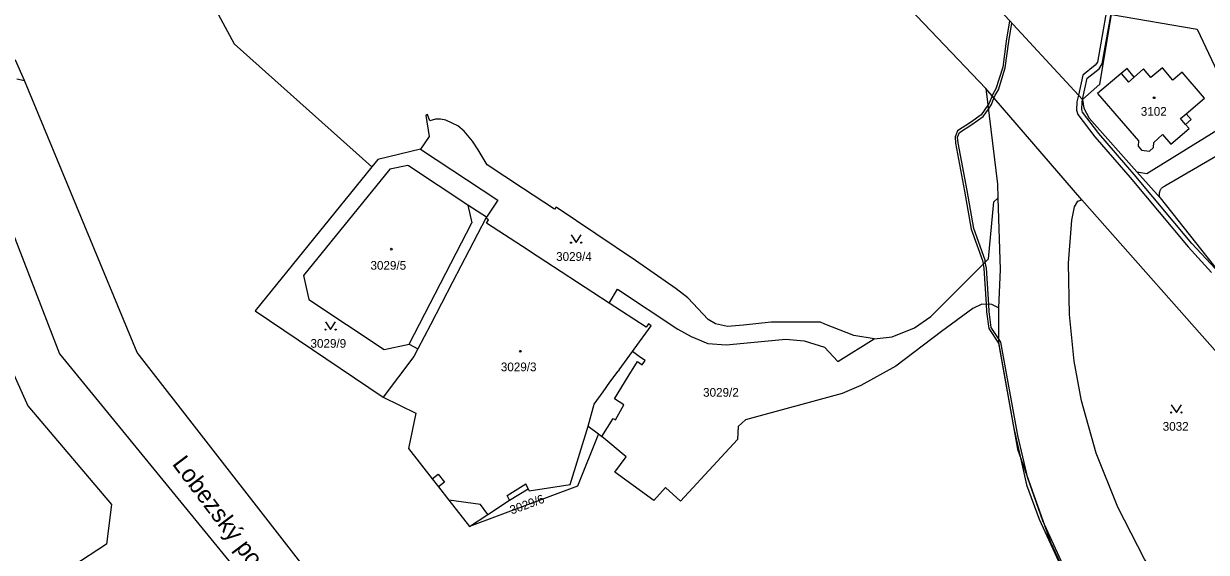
# Model space of a CAD drawing. Extents: x -869103 to -863415, y -1015889 to -1012477.
# Drawn here: x -866992.3 to -866761.8, y -1014341 to -1014238 of the extents above; entities that cross this region are included whole.
import ezdxf

# ---------------------------------------------------------------- set-up
doc = ezdxf.new("R2010")
doc.units = 0
for name, color, linetype in [('Hranice parcel', 7, 'Continuous'), ('Parcelní čísla', 7, 'Continuous'), ('Pop  PČ popisy', 7, 'Continuous'), ('Vnitřní kresba', 7, 'Continuous'), ('Věcná břemena k části', 7, 'Continuous'), ('Značky budov', 7, 'Continuous'), ('Značky kultur', 7, 'Continuous')]:
    doc.layers.add(name, color=color, linetype=linetype)

msp = doc.modelspace()

# ---------------------------------------------------------------- linework, layer by layer
at = {"layer": 'Hranice parcel'}
for p, q in [((-866964.38, -1014217.69), (-866951.31, -1014241.98)), ((-866802.65, -1014234.76), (-866785.95, -1014252.79)), ((-866951.31, -1014241.98), (-866924.44, -1014265.92)), ((-866970.19, -1014302.07), (-866992.13, -1014249.12)), ((-866786.04, -1014272.37), (-866804.77, -1014250.67)), ((-866802.4, -1014272.01), (-866801.98, -1014285.91)), ((-866786.04, -1014272.37), (-866743.88, -1014320.01)), ((-866902.08, -1014275.74), (-866902.24, -1014275.9)), ((-866801.98, -1014285.91), (-866802.31, -1014293.4)), ((-866880.29, -1014317.92), (-866879.64, -1014318.4))]:
    msp.add_line(p, q, dxfattribs=at)
for points in [[(-867024.12, -1014103.23), (-867025.22, -1014106.66), (-867026.7, -1014110.06), (-867027.68, -1014113.98), (-867028.22, -1014118.6), (-867028.54, -1014131.39), (-867028.57, -1014139.98), (-867029.17, -1014140.61), (-867028.61, -1014175.02), (-867028.14, -1014185.17), (-867027.28, -1014193.35), (-867026.52, -1014197.65), (-867025.07, -1014203.92), (-867022.09, -1014213.15), (-867017.38, -1014224.52), (-867004.44, -1014249.09), (-867006.1, -1014248.94), (-867004.52, -1014252.89), (-867004.05, -1014254.08), (-866985.31, -1014302.3), (-866931.57, -1014367.99)], [(-866992.13, -1014249.12), (-866993.94, -1014245.11), (-866995.31, -1014245.64), (-867000.95, -1014239.81), (-867007.7, -1014227.79), (-867011.08, -1014220.99), (-867014.34, -1014213.16), (-867017.24, -1014203.32), (-867020.06, -1014192.16), (-867021.01, -1014182.17), (-867021.12, -1014175.42), (-867020.1, -1014140.5)], [(-866785.95, -1014252.79), (-866782.53, -1014249.83), (-866780.28, -1014236.23), (-866774.28, -1014200.77)], [(-866804.77, -1014250.67), (-866827.62, -1014226.66), (-866838.88, -1014204.15)], [(-866772.86, -1014262.83), (-866772.07, -1014262.16), (-866772.04, -1014261.16), (-866770.36, -1014259.62), (-866768.71, -1014261.53), (-866765.14, -1014258.44), (-866765.82, -1014257.65), (-866764.74, -1014256.72), (-866765.71, -1014255.58), (-866762.17, -1014252.56), (-866766.52, -1014247.5), (-866768.29, -1014249.01), (-866770.33, -1014246.6), (-866772.58, -1014248.54), (-866774.02, -1014246.85), (-866775.84, -1014248.42), (-866777.2, -1014246.74), (-866778.37, -1014247.73), (-866782.99, -1014251.61), (-866775, -1014260.85), (-866775.09, -1014261.92), (-866774.44, -1014262.65), (-866772.86, -1014262.83)], [(-866804.77, -1014250.67), (-866802.48, -1014269.28), (-866802.4, -1014272.01)], [(-866785.95, -1014252.79), (-866785.66, -1014254.51), (-866784.65, -1014256.46), (-866775.31, -1014266.88), (-866770.78, -1014271.95), (-866748.88, -1014299.59)], [(-866826.54, -1014299.41), (-866830.52, -1014298.76), (-866836.15, -1014296.55), (-866837.01, -1014296.17), (-866846.62, -1014296.18), (-866852.01, -1014296.78), (-866855.15, -1014297.04), (-866857.48, -1014296.47), (-866858.89, -1014295.66), (-866862.85, -1014291.42), (-866865.11, -1014289.65), (-866873.08, -1014284.15), (-866888.52, -1014273.74), (-866888.83, -1014274.16), (-866895.1, -1014270.06), (-866901.95, -1014265.51), (-866903.72, -1014262.58), (-866904.81, -1014260.94), (-866906.45, -1014258.96), (-866907.69, -1014257.96), (-866908.79, -1014257.38), (-866910.01, -1014256.84), (-866911.07, -1014256.65), (-866912.04, -1014256.65), (-866913.17, -1014256.95), (-866913.61, -1014255.7), (-866913.96, -1014255.91), (-866913.31, -1014260.01), (-866914.94, -1014262.48)], [(-866914.94, -1014262.48), (-866923.29, -1014264.5), (-866924.44, -1014265.92)], [(-866914.94, -1014262.48), (-866899.88, -1014272.4), (-866902.08, -1014275.74)], [(-866924.44, -1014265.92), (-866947.22, -1014293.94), (-866922.25, -1014310.74)], [(-866902.08, -1014275.74), (-866905.72, -1014273.37), (-866917.32, -1014265.7), (-866917.42, -1014265.66), (-866920.96, -1014266.39), (-866937.78, -1014287.08), (-866936.73, -1014291.78), (-866922.04, -1014301.49), (-866917.2, -1014300.45), (-866915.47, -1014301.35)], [(-866815.46, -1014295.07), (-866804.23, -1014283.81), (-866803.19, -1014272.71), (-866802.4, -1014272.01)], [(-867008.33, -1014274.01), (-867004.45, -1014276.58), (-866995.06, -1014304.46), (-866991.53, -1014312.47), (-866975.18, -1014331.69), (-866976.17, -1014339.4), (-866989.29, -1014348), (-867029.58, -1014342.1), (-867038.07, -1014339.07), (-867056.98, -1014311.75)], [(-866763.74, -1014351.64), (-866766.16, -1014351.83), (-866767.82, -1014351.02), (-866769.8, -1014348.61), (-866773.81, -1014342.3), (-866779.03, -1014332.18), (-866783.24, -1014321.66), (-866786.09, -1014311.51), (-866787.58, -1014303.77), (-866788.49, -1014294.7), (-866788.64, -1014284.67), (-866787.99, -1014276.32), (-866787.46, -1014273.73), (-866786.86, -1014272.6), (-866786.04, -1014272.37)], [(-866902.24, -1014275.9), (-866908.74, -1014288.39), (-866913.05, -1014296.66), (-866915.47, -1014301.35)], [(-866878.22, -1014292.44), (-866893.73, -1014282.34), (-866893.98, -1014282.17), (-866902.09, -1014276.88), (-866901.69, -1014276.26), (-866902.24, -1014275.9)], [(-866878.22, -1014292.44), (-866876.58, -1014289.73), (-866864.81, -1014297.51), (-866862.18, -1014298.98), (-866858.93, -1014300.33), (-866855.36, -1014300.6), (-866843.73, -1014299.46), (-866840.19, -1014299.77), (-866836.24, -1014301.05), (-866833.62, -1014303.81), (-866826.54, -1014299.41)], [(-866879.64, -1014318.4), (-866877.38, -1014314.9), (-866876.99, -1014315.16), (-866875.32, -1014312.29), (-866877.16, -1014311.1), (-866874.49, -1014306.74), (-866872.64, -1014303.85), (-866871.77, -1014304.46), (-866871.19, -1014303.64), (-866872.06, -1014303.03), (-866873.66, -1014301.9), (-866873.32, -1014301.43), (-866869.99, -1014296.86), (-866870.54, -1014296.51), (-866870.97, -1014297.17), (-866878.22, -1014292.44)], [(-866802.31, -1014293.4), (-866803.61, -1014292.75), (-866805.56, -1014292.65), (-866807.33, -1014293.48), (-866813.39, -1014297.98), (-866822.34, -1014304.75), (-866829.11, -1014308.49), (-866832.75, -1014310.07), (-866851.61, -1014315.16), (-866853.07, -1014316.47), (-866853.16, -1014318.99), (-866864.28, -1014331.05), (-866867.22, -1014328.39), (-866869.49, -1014330.91), (-866877.08, -1014325.4), (-866874.87, -1014322.38), (-866879.64, -1014318.4)], [(-866826.54, -1014299.41), (-866823.04, -1014299), (-866818.65, -1014297.26), (-866815.46, -1014295.07)], [(-866802.31, -1014293.4), (-866802.32, -1014300.1), (-866798.61, -1014320.9), (-866792.16, -1014339.01)], [(-866894.48, -1014395.42), (-866902.57, -1014388.88), (-866902.97, -1014388.36), (-866903.86, -1014387.22), (-866970.19, -1014302.07)], [(-866915.47, -1014301.35), (-866916.28, -1014302.87), (-866922.25, -1014310.74)], [(-866922.25, -1014310.74), (-866915.88, -1014313.9), (-866917.3, -1014320.74), (-866912.67, -1014326.67), (-866911.44, -1014328.23), (-866909.42, -1014330.82), (-866905.39, -1014335.98)], [(-866905.39, -1014335.98), (-866901.82, -1014333.6), (-866897.59, -1014330.84), (-866893.97, -1014328.62), (-866893.77, -1014329.02), (-866885.78, -1014327.77), (-866882.31, -1014316.43), (-866880.29, -1014317.92)], [(-866880.29, -1014317.92), (-866884.36, -1014328.09), (-866905.39, -1014335.98)], [(-866792.16, -1014339.01), (-866779.26, -1014366.65), (-866778.45, -1014367.75)]]:
    msp.add_lwpolyline(points, dxfattribs=at)
at = {"layer": 'Vnitřní kresba'}
for p, q in [((-866780.28, -1014236.23), (-866763.6, -1014239.07)), ((-866763.6, -1014239.07), (-866756.87, -1014253.24)), ((-866993.66, -1014248.76), (-866992.13, -1014249.12)), ((-866778.37, -1014247.73), (-866776.93, -1014249.43)), ((-866776.93, -1014249.43), (-866775.84, -1014248.42)), ((-866766.8, -1014256.51), (-866765.71, -1014255.58)), ((-866765.82, -1014257.65), (-866766.8, -1014256.51)), ((-866773.36, -1014267.18), (-866759.41, -1014258.6)), ((-866769.86, -1014269.62), (-866757.11, -1014262.24)), ((-866775.31, -1014266.88), (-866773.36, -1014267.18)), ((-866905.72, -1014273.37), (-866904.98, -1014276.85)), ((-866917.2, -1014300.45), (-866904.98, -1014276.85)), ((-866876.26, -1014305.45), (-866873.66, -1014301.9)), ((-866878.03, -1014307.87), (-866876.43, -1014305.68)), ((-866876.26, -1014305.45), (-866876.43, -1014305.68)), ((-866879.39, -1014309.74), (-866878.03, -1014307.87)), ((-866881.12, -1014312.11), (-866879.39, -1014309.74)), ((-866882.31, -1014316.43), (-866881.12, -1014312.11)), ((-866912.67, -1014326.67), (-866911.52, -1014325.77)), ((-866911.52, -1014325.77), (-866910.31, -1014327.32)), ((-866910.31, -1014327.32), (-866911.44, -1014328.23)), ((-866898.08, -1014329.94), (-866894.45, -1014327.66)), ((-866893.97, -1014328.62), (-866894.45, -1014327.66)), ((-866903.26, -1014331.7), (-866909.42, -1014330.82)), ((-866901.82, -1014333.6), (-866903.26, -1014331.7)), ((-866897.59, -1014330.84), (-866898.08, -1014329.94))]:
    msp.add_line(p, q, dxfattribs=at)
msp.add_lwpolyline([(-866770.78, -1014271.95), (-866770.82, -1014271.84), (-866770.86, -1014271.73), (-866770.89, -1014271.62), (-866770.91, -1014271.51), (-866770.92, -1014271.39), (-866770.93, -1014271.27), (-866770.93, -1014271.16), (-866770.92, -1014271.04), (-866770.9, -1014270.93), (-866770.87, -1014270.82), (-866770.84, -1014270.7), (-866770.8, -1014270.59), (-866770.76, -1014270.49), (-866770.7, -1014270.39), (-866770.64, -1014270.29), (-866770.58, -1014270.19), (-866770.51, -1014270.1), (-866770.43, -1014270.01), (-866770.34, -1014269.93), (-866770.26, -1014269.86), (-866770.16, -1014269.79), (-866770.07, -1014269.73), (-866769.96, -1014269.67), (-866769.86, -1014269.62)], dxfattribs=at)
at = {"layer": 'Věcná břemena k části'}
for points in [[(-866780.33, -1014230.29), (-866783.03, -1014245.5), (-866783.44, -1014246.14), (-866785.89, -1014248.07), (-866786.72, -1014251.95), (-866787, -1014253.24), (-866787.08, -1014254.86), (-866786.81, -1014255.7), (-866783.54, -1014260.06), (-866776.61, -1014268.02), (-866765.36, -1014281.48), (-866760.75, -1014286.47)], [(-866759.99, -1014285.81), (-866764.6, -1014280.82), (-866775.85, -1014267.38), (-866782.76, -1014259.44), (-866785.91, -1014255.24), (-866786.08, -1014254.72), (-866786, -1014253.38), (-866785.95, -1014252.79), (-866784.99, -1014248.63), (-866782.68, -1014246.82), (-866782.07, -1014245.87), (-866779.31, -1014230.23)], [(-866800.14, -1014237.47), (-866800.81, -1014241.42), (-866801.48, -1014246.52), (-866802.79, -1014250.71), (-866803.42, -1014251.76), (-866803.55, -1014252.09), (-866804.12, -1014253.54), (-866804.37, -1014253.9), (-866805.67, -1014255.77), (-866807.78, -1014257.28), (-866810.32, -1014258.88), (-866810.77, -1014260.05), (-866810.69, -1014261.29), (-866808.91, -1014270.62), (-866807.6, -1014278.05), (-866805.41, -1014284.18), (-866805.3, -1014284.89), (-866805.17, -1014285.74), (-866804.71, -1014292.69), (-866804.62, -1014294.17), (-866804.18, -1014297.39), (-866802.29, -1014300.27), (-866799.39, -1014316.54), (-866798.02, -1014322.56), (-866796.82, -1014327.83), (-866794.35, -1014334.51), (-866790.22, -1014343.55)], [(-866800.14, -1014237.47), (-866800.81, -1014241.42), (-866801.48, -1014246.52), (-866802.79, -1014250.71), (-866803.42, -1014251.76), (-866803.55, -1014252.09), (-866804.12, -1014253.54), (-866804.37, -1014253.9), (-866805.67, -1014255.77), (-866807.78, -1014257.28), (-866810.32, -1014258.88), (-866810.77, -1014260.05), (-866810.69, -1014261.29), (-866808.91, -1014270.62), (-866807.6, -1014278.05), (-866805.41, -1014284.18), (-866805.3, -1014284.89), (-866805.17, -1014285.74), (-866804.71, -1014292.69), (-866804.62, -1014294.17), (-866804.18, -1014297.39), (-866802.29, -1014300.27), (-866799.39, -1014316.54), (-866798.02, -1014322.56), (-866796.82, -1014327.83), (-866794.35, -1014334.51), (-866790.22, -1014343.55)], [(-866789.74, -1014343.39), (-866793.63, -1014334.87), (-866796.6, -1014326.54), (-866798.5, -1014318.21), (-866801.83, -1014300.05), (-866802.32, -1014299.32), (-866803.7, -1014297.21), (-866804.12, -1014294.11), (-866804.21, -1014292.72), (-866804.67, -1014285.68), (-866804.87, -1014284.45), (-866804.93, -1014284.06), (-866807.12, -1014277.93), (-866808.41, -1014270.52), (-866810.19, -1014261.23), (-866810.27, -1014260.13), (-866809.92, -1014259.22), (-866807.5, -1014257.7), (-866805.31, -1014256.13), (-866804.28, -1014254.65), (-866803.68, -1014253.78), (-866803.18, -1014252.52), (-866802.96, -1014251.98), (-866802.33, -1014250.91), (-866800.98, -1014246.62), (-866800.31, -1014241.5), (-866799.71, -1014237.94)], [(-866789.74, -1014343.39), (-866793.63, -1014334.87), (-866796.6, -1014326.54), (-866798.5, -1014318.21), (-866801.83, -1014300.05), (-866802.32, -1014299.32), (-866803.7, -1014297.21), (-866804.12, -1014294.11), (-866804.21, -1014292.72), (-866804.67, -1014285.68), (-866804.87, -1014284.45), (-866804.93, -1014284.06), (-866807.12, -1014277.93), (-866808.41, -1014270.52), (-866810.19, -1014261.23), (-866810.27, -1014260.13), (-866809.92, -1014259.22), (-866807.5, -1014257.7), (-866805.31, -1014256.13), (-866804.28, -1014254.65), (-866803.68, -1014253.78), (-866803.18, -1014252.52), (-866802.96, -1014251.98), (-866802.33, -1014250.91), (-866800.98, -1014246.62), (-866800.31, -1014241.5), (-866799.71, -1014237.94)]]:
    msp.add_lwpolyline(points, dxfattribs=at)
at = {"layer": 'Značky budov'}
for centre in [(-866771.97, -1014252.46), (-866920.66, -1014281.96), (-866895.51, -1014301.83)]:
    msp.add_circle(centre, 0.175, dxfattribs=at)
at = {"layer": 'Značky kultur'}
for points in [[(-866885.63, -1014279.18), (-866884.63, -1014280.68), (-866883.63, -1014279.18)], [(-866933.51, -1014296.1), (-866932.51, -1014297.6), (-866931.51, -1014296.1)], [(-866768.62, -1014312.26), (-866767.62, -1014313.76), (-866766.62, -1014312.26)]]:
    msp.add_lwpolyline(points, dxfattribs=at)
for centre in [(-866885.63, -1014280.68), (-866883.63, -1014280.68), (-866933.51, -1014297.6), (-866931.51, -1014297.6), (-866768.62, -1014313.76), (-866766.62, -1014313.76)]:
    msp.add_circle(centre, 0.1, dxfattribs=at)

# ---------------------------------------------------------------- texts
at = {"layer": 'Parcelní čísla'}
for s, p in [('3102', (-866774.56, -1014255.97)), ('3029/4', (-866888.53, -1014284.23)), ('3029/5', (-866924.72, -1014285.95)), ('3029/9', (-866936.41, -1014301.15)), ('3029/3', (-866899.31, -1014305.73)), ('3029/2', (-866859.88, -1014310.69)), ('3032', (-866770.29, -1014317.31))]:
    msp.add_text(s, height=1.7, dxfattribs=at).set_placement(p)
msp.add_text('3029/6', height=1.7, rotation=20, dxfattribs=at).set_placement((-866897.19, -1014333.64))
at = {"layer": 'Pop  PČ popisy'}
msp.add_text('Lobezský potok', height=3.4, rotation=307, dxfattribs=at).set_placement((-866963.49, -1014323.79))

doc.saveas('drawing.dxf')
